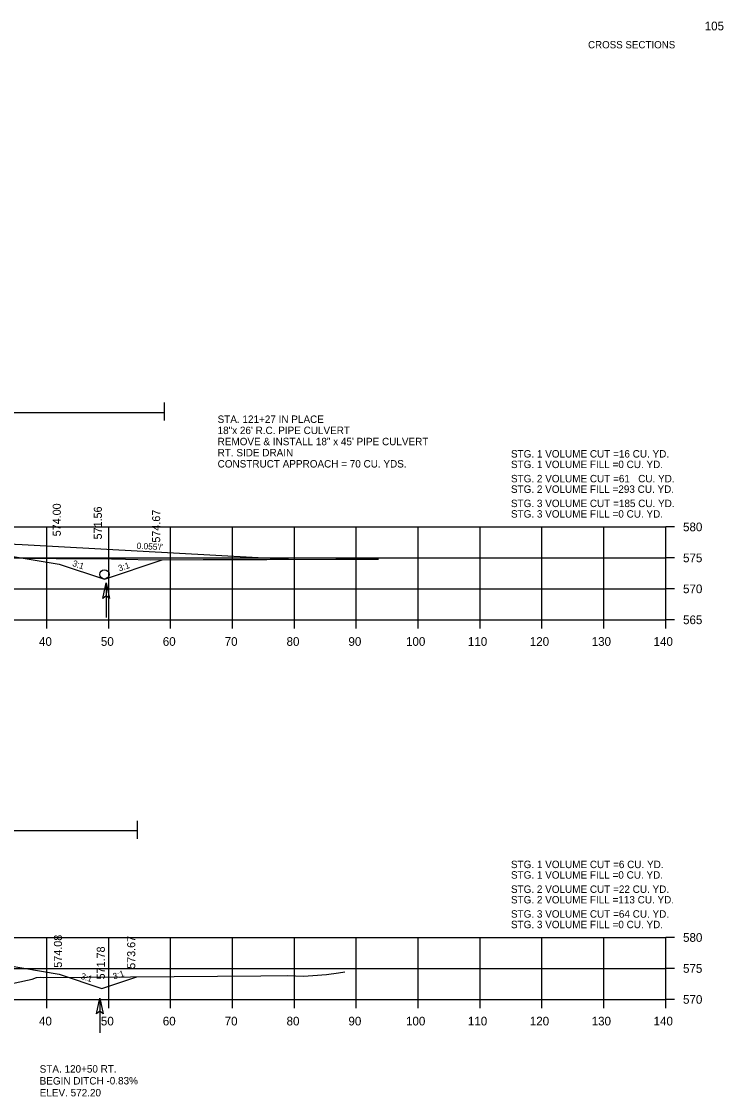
# Model space of a CAD drawing. Extents: x 642114 to 642416, y 286928 to 293347.
# Drawn here: x 642296.2 to 642409.6, y 290952 to 291125.6 of the extents above; entities that cross this region are included whole.
import ezdxf

# ---------------------------------------------------------------- set-up
doc = ezdxf.new("R2010")
doc.units = 0
for name, color, linetype in [('59', 7, 'Continuous'), ('Level 24', 7, 'Continuous'), ('Level 43', 7, 'Continuous'), ('Level 58', 7, 'Continuous'), ('R_Axis', 7, 'Continuous'), ('R_Axis Annot', 7, 'Continuous'), ('R_Border', 7, 'Continuous'), ('R_Border Notes', 7, 'Continuous'), ('R_Draft', 7, 'Continuous'), ('R_Drive', 7, 'Continuous'), ('R_Exist Surface Annot', 7, 'Continuous'), ('R_Fin Surface', 7, 'Continuous'), ('R_Grid', 7, 'Continuous'), ('R_Xsect Elev', 7, 'Continuous'), ('R_Xsect Slope', 7, 'Continuous')]:
    doc.layers.add(name, color=color, linetype=linetype)

# ---------------------------------------------------------------- blocks, each defined once
blk = doc.blocks.new('FA')
at = {"layer": 'Level 43'}
blk.add_lwpolyline([(7.94, 0), (0, 0)], dxfattribs=at)
at = {"layer": 'Level 58'}
blk.add_lwpolyline([(4.34, 0.75), (7.94, 0), (4.34, -0.75), (4.94, 0)], close=True, dxfattribs=at)

msp = doc.modelspace()

# ---------------------------------------------------------------- linework, layer by layer
at = {"layer": 'R_Axis'}
for p, q in [((642400.24, 291028.95), (642400.24, 291043.95)), ((642401.64, 291043.95), (642400.24, 291043.95)), ((642401.64, 291038.95), (642400.24, 291038.95)), ((642401.64, 291033.95), (642400.24, 291033.95)), ((642120.24, 291028.95), (642400.24, 291028.95)), ((642300.24, 291027.55), (642300.24, 291028.95)), ((642310.24, 291027.55), (642310.24, 291028.95)), ((642320.24, 291027.55), (642320.24, 291028.95)), ((642330.24, 291027.55), (642330.24, 291028.95)), ((642340.24, 291027.55), (642340.24, 291028.95)), ((642350.24, 291027.55), (642350.24, 291028.95)), ((642360.24, 291027.55), (642360.24, 291028.95)), ((642370.24, 291027.55), (642370.24, 291028.95)), ((642380.24, 291027.55), (642380.24, 291028.95)), ((642390.24, 291027.55), (642390.24, 291028.95)), ((642400.24, 291027.55), (642400.24, 291028.95)), ((642401.64, 291028.95), (642400.24, 291028.95)), ((642400.24, 290967.66), (642400.24, 290977.66)), ((642401.64, 290977.66), (642400.24, 290977.66)), ((642401.64, 290972.66), (642400.24, 290972.66)), ((642120.24, 290967.66), (642400.24, 290967.66)), ((642300.24, 290966.26), (642300.24, 290967.66)), ((642310.24, 290966.26), (642310.24, 290967.66)), ((642320.24, 290966.26), (642320.24, 290967.66)), ((642330.24, 290966.26), (642330.24, 290967.66)), ((642340.24, 290966.26), (642340.24, 290967.66)), ((642350.24, 290966.26), (642350.24, 290967.66)), ((642360.24, 290966.26), (642360.24, 290967.66)), ((642370.24, 290966.26), (642370.24, 290967.66)), ((642380.24, 290966.26), (642380.24, 290967.66)), ((642390.24, 290966.26), (642390.24, 290967.66)), ((642400.24, 290966.26), (642400.24, 290967.66)), ((642401.64, 290967.66), (642400.24, 290967.66))]:
    msp.add_line(p, q, dxfattribs=at)
at = {"layer": 'R_Drive'}
msp.add_lwpolyline([(642296.24, 291041.1), (642340.24, 291038.7)], dxfattribs=at)
at = {"layer": 'R_Exist Surface Annot'}
for points in [[(642291.45, 291038.97), (642301.77, 291038.85), (642308.4, 291038.83), (642312.96, 291038.73), (642316.97, 291038.62), (642325.48, 291038.67), (642335.78, 291038.67), (642346.92, 291038.74), (642353.86, 291038.75)], [(642291.1, 290969.48), (642297.87, 290970.93), (642298.6, 290971.18), (642299.17, 290971.24), (642299.74, 290971.22), (642334.84, 290971.48), (642339.13, 290971.5), (642341.71, 290971.42), (642343.22, 290971.53), (642345.44, 290971.68), (642347.37, 290971.95), (642348.37, 290972.09)]]:
    msp.add_lwpolyline(points, dxfattribs=at)
at = {"layer": 'R_Fin Surface'}
for points in [[(642280.24, 291041.62), (642283.43, 291041.09), (642288.23, 291040.29), (642293.83, 291039.35), (642302.24, 291037.95), (642309.55, 291035.51), (642318.89, 291038.63)], [(642286.24, 291041.6), (642296.24, 291041.1)], [(642280.24, 290975.41), (642288.23, 290974.08), (642302.24, 290971.74)], [(642302.24, 290971.74), (642309.14, 290969.44), (642314.79, 290971.33)]]:
    msp.add_lwpolyline(points, dxfattribs=at)
msp.add_circle((642309.55, 291036.29), 0.75, dxfattribs=at)
at = {"layer": 'R_Grid'}
for p, q in [((642120.24, 291043.95), (642400.24, 291043.95)), ((642300.24, 291028.95), (642300.24, 291043.95)), ((642310.24, 291028.95), (642310.24, 291043.95)), ((642320.24, 291028.95), (642320.24, 291043.95)), ((642330.24, 291028.95), (642330.24, 291043.95)), ((642340.24, 291028.95), (642340.24, 291043.95)), ((642350.24, 291028.95), (642350.24, 291043.95)), ((642360.24, 291028.95), (642360.24, 291043.95)), ((642370.24, 291028.95), (642370.24, 291043.95)), ((642380.24, 291028.95), (642380.24, 291043.95)), ((642390.24, 291028.95), (642390.24, 291043.95)), ((642400.24, 291028.95), (642400.24, 291043.95)), ((642120.24, 291038.95), (642400.24, 291038.95)), ((642120.24, 291033.95), (642400.24, 291033.95)), ((642120.24, 291028.95), (642400.24, 291028.95)), ((642120.24, 290977.66), (642400.24, 290977.66)), ((642300.24, 290967.66), (642300.24, 290977.66)), ((642310.24, 290967.66), (642310.24, 290977.66)), ((642320.24, 290967.66), (642320.24, 290977.66)), ((642330.24, 290967.66), (642330.24, 290977.66)), ((642340.24, 290967.66), (642340.24, 290977.66)), ((642350.24, 290967.66), (642350.24, 290977.66)), ((642360.24, 290967.66), (642360.24, 290977.66)), ((642370.24, 290967.66), (642370.24, 290977.66)), ((642380.24, 290967.66), (642380.24, 290977.66)), ((642390.24, 290967.66), (642390.24, 290977.66)), ((642400.24, 290967.66), (642400.24, 290977.66)), ((642120.24, 290972.66), (642400.24, 290972.66)), ((642120.24, 290967.66), (642400.24, 290967.66))]:
    msp.add_line(p, q, dxfattribs=at)
at = {"layer": 'R_Xsect Elev'}
for p, q in [((642319.24, 291061.12), (642319.24, 291064.05)), ((642239.39, 291062.45), (642319.24, 291062.45)), ((642238.26, 290994.91), (642314.9, 290994.91)), ((642314.9, 290993.58), (642314.9, 290996.5))]:
    msp.add_line(p, q, dxfattribs=at)

# ---------------------------------------------------------------- block references
at = {"layer": 'R_Xsect Elev', "xscale": 0.7, "yscale": 0.7, "rotation": 89.99999999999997}
for p in [(642309.84, 291029.34), (642308.81, 290962.28)]:
    msp.add_blockref('FA', p, dxfattribs=at)

# ---------------------------------------------------------------- texts
at = {"layer": '59'}
for s, p in [(' 574.00', (642302.5, 291041.95)), (' 571.56', (642309.14, 291041.45)), (' 574.67', (642318.56, 291040.93)), (' 574.08', (642302.69, 290972.3)), (' 573.67', (642314.53, 290972.12)), (' 571.78', (642309.62, 290970.41))]:
    msp.add_text(s, height=1.3, rotation=90, dxfattribs=at).set_placement(p)
at = {"layer": 'Level 24'}
for s, p in [('STA. 121+27 IN PLACE', (642327.84, 291060.74)), ('18"x 26\' R.C. PIPE CULVERT', (642327.84, 291058.94)), ('REMOVE & INSTALL 18" x 45\' PIPE CULVERT', (642327.84, 291057.14)), ('RT. SIDE DRAIN', (642327.84, 291055.34)), ('CONSTRUCT APPROACH = 70 CU. YDS.', (642327.84, 291053.54))]:
    msp.add_text(s, height=1.2, rotation=0.0044, dxfattribs=at).set_placement(p)
at = {"layer": 'R_Axis Annot'}
for s, p in [('580', (642403.04, 291043.25)), ('575', (642403.04, 291038.25)), ('570', (642403.04, 291033.25)), ('565', (642403.04, 291028.25)), ('40', (642298.98, 291024.75)), ('50', (642308.98, 291024.75)), ('60', (642318.98, 291024.75)), ('70', (642328.98, 291024.75)), ('80', (642338.98, 291024.75)), ('90', (642348.98, 291024.75)), ('100', (642358.28, 291024.75)), ('110', (642368.28, 291024.75)), ('120', (642378.28, 291024.75)), ('130', (642388.28, 291024.75)), ('140', (642398.28, 291024.75)), ('580', (642403.04, 290976.96)), ('575', (642403.04, 290971.96)), ('570', (642403.04, 290966.96)), ('40', (642298.98, 290963.46)), ('50', (642308.98, 290963.46)), ('60', (642318.98, 290963.46)), ('70', (642328.98, 290963.46)), ('80', (642338.98, 290963.46)), ('90', (642348.98, 290963.46)), ('100', (642358.28, 290963.46)), ('110', (642368.28, 290963.46)), ('120', (642378.28, 290963.46)), ('130', (642388.28, 290963.46)), ('140', (642398.28, 290963.46))]:
    msp.add_text(s, height=1.4, dxfattribs=at).set_placement(p)
at = {"layer": 'R_Border'}
msp.add_text('105', height=1.4, dxfattribs=at).set_placement((642406.54, 291124.13))
at = {"layer": 'R_Border Notes'}
msp.add_text('    CROSS SECTIONS    ', height=1.178, dxfattribs=at).set_placement((642385.94, 291121.22))
at = {"layer": 'R_Draft'}
for s, p in [('STG. 1 VOLUME CUT =16 CU. YD.', (642375.24, 291055.15)), ('STG. 1 VOLUME FILL =0 CU. YD.', (642375.24, 291053.45)), ('STG. 2 VOLUME CUT =61   CU. YD.', (642375.24, 291051.15)), ('STG. 2 VOLUME FILL =293 CU. YD.', (642375.24, 291049.45)), ('STG. 3 VOLUME CUT =185 CU. YD.', (642375.24, 291047.15)), ('STG. 3 VOLUME FILL =0 CU. YD.', (642375.24, 291045.45)), ('STG. 1 VOLUME CUT =6 CU. YD.', (642375.24, 290988.86)), ('STG. 1 VOLUME FILL =0 CU. YD.', (642375.24, 290987.16)), ('STG. 2 VOLUME CUT =22 CU. YD.', (642375.24, 290984.86)), ('STG. 2 VOLUME FILL =113 CU. YD.', (642375.24, 290983.16)), ('STG. 3 VOLUME CUT =64 CU. YD.', (642375.24, 290980.86)), ('STG. 3 VOLUME FILL =0 CU. YD.', (642375.24, 290979.16))]:
    msp.add_text(s, height=1.2, dxfattribs=at).set_placement(p)
at = {"layer": 'R_Xsect Elev'}
for s, p in [('STA. 120+50 RT.', (642299.09, 290955.83)), ('BEGIN DITCH -0.83%', (642299.09, 290953.91)), ('ELEV. 572.20', (642299.1, 290951.99))]:
    msp.add_text(s, height=1.2, rotation=0.107, dxfattribs=at).set_placement(p)
at = {"layer": 'R_Xsect Slope'}
for s, rotation, p in [("0.055'/'", 356.8582, (642314.74, 291040.42)), ('3:1', 341.5668, (642304.3, 291037.67)), ('3:1', 18.4332, (642311.97, 291036.76)), ('3:1', 18.4332, (642311.1, 290970.86)), ('3:1', 341.5668, (642305.64, 290971.02))]:
    msp.add_text(s, height=1, rotation=rotation, dxfattribs=at).set_placement(p)

doc.saveas('drawing.dxf')
